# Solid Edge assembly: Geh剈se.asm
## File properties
Author: heha
Template: Normal.asm
Last saved by: heha
Revision: 1
Application: Solid Edge
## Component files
Blech vorn.psm
Seite.par
Blech hinten.psm
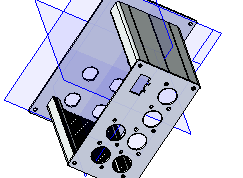
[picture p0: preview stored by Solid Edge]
